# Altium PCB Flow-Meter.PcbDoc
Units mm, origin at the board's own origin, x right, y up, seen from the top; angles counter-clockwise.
Board outline 17 x 19 mm, 2 copper layers (Top Layer, Bottom Layer), stack 1.571 mm thick; 12 components, 7 nets, 36 pads, 15 vias.
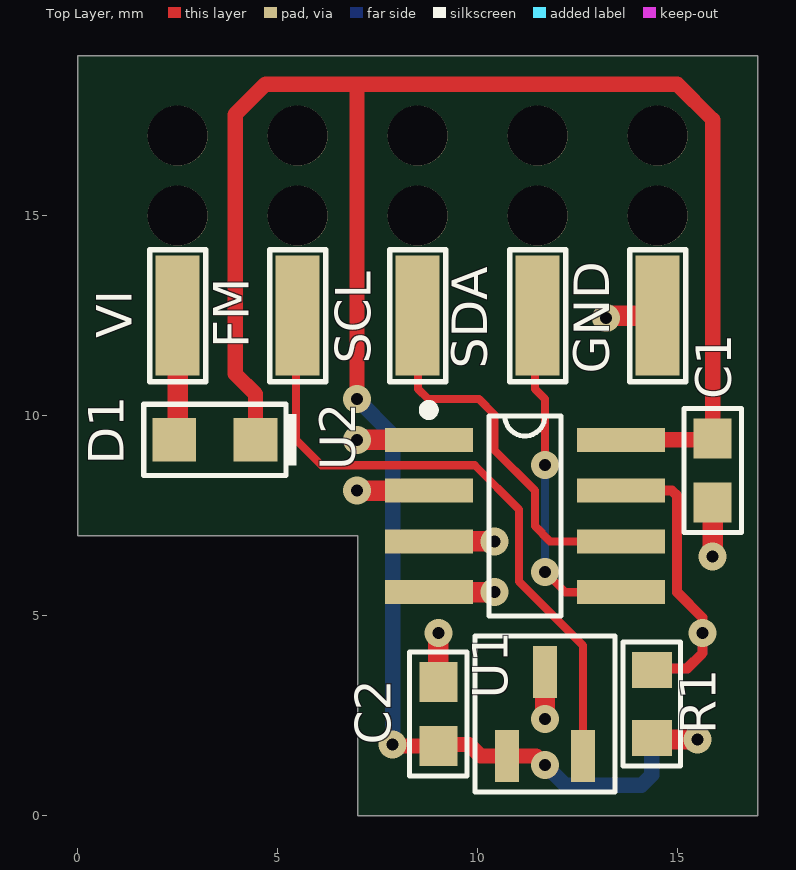
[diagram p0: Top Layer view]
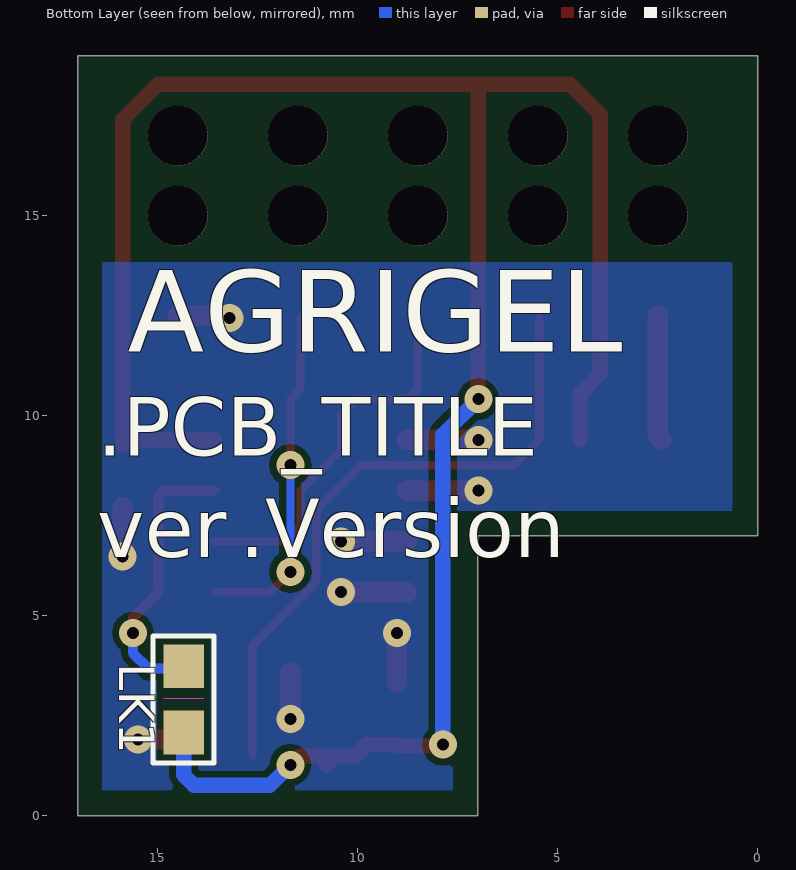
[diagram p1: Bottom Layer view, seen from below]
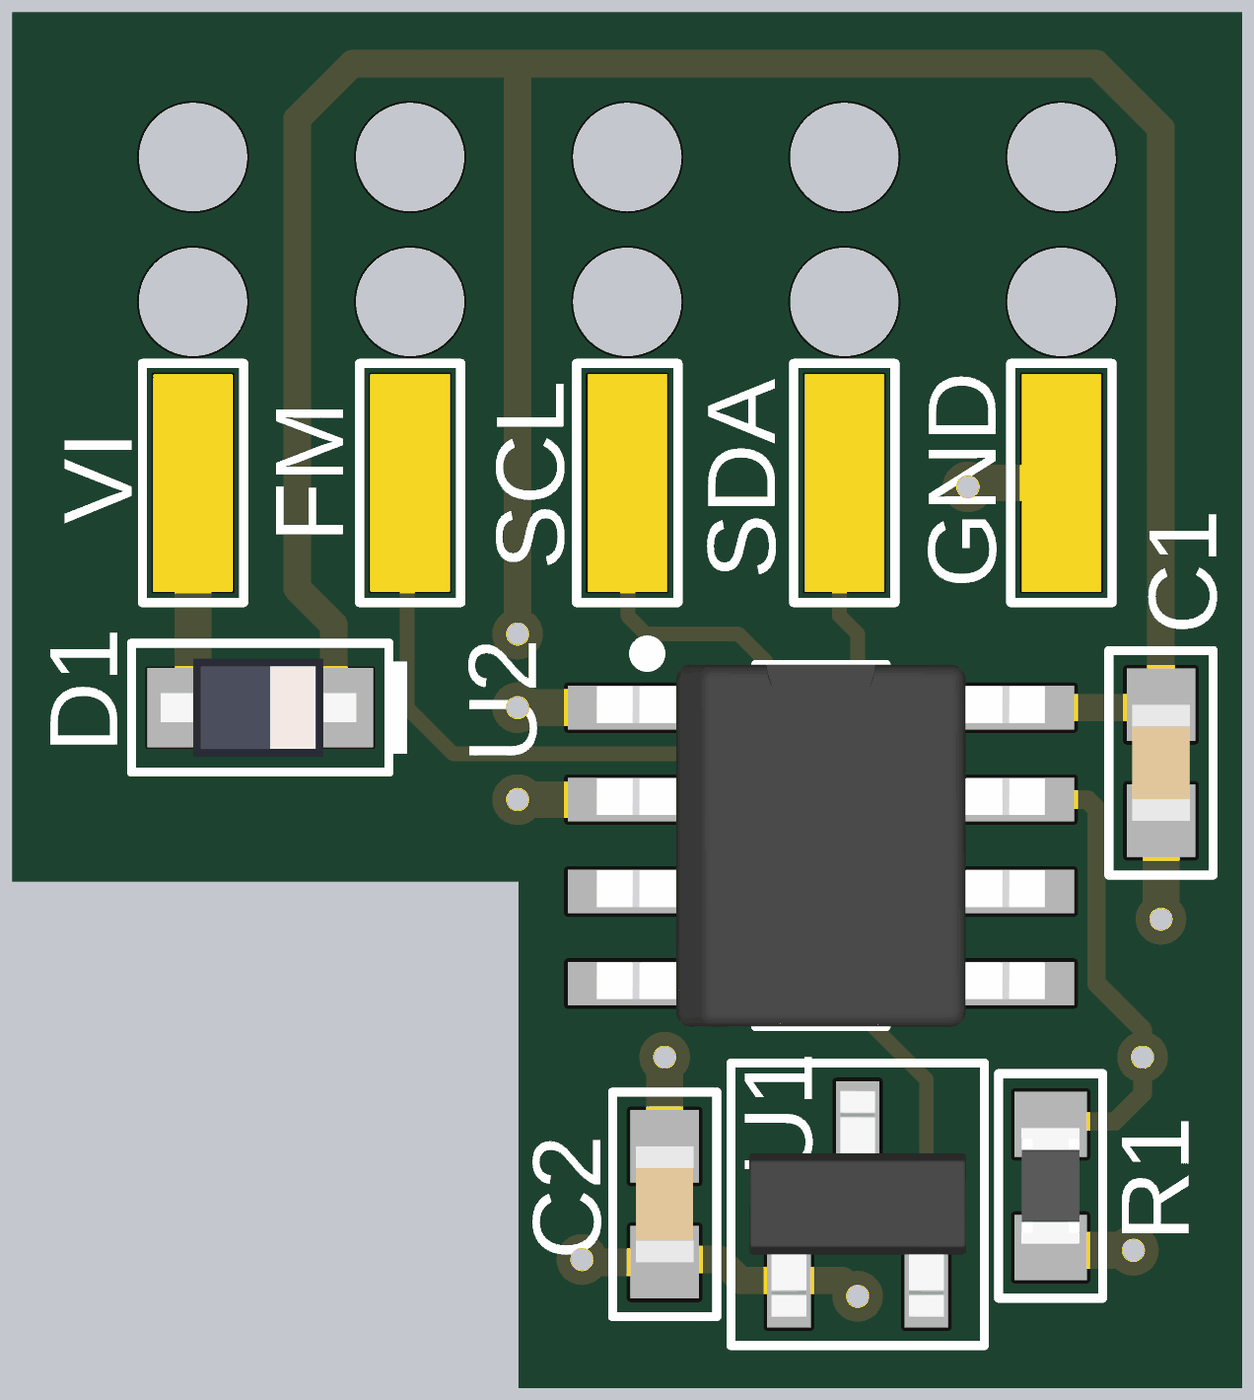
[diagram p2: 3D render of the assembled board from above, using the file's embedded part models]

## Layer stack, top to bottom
Top Layer: signal copper 0.0356
Dielectric: prepreg 1.5, FR-4, Dk 4.2
Bottom Layer: signal copper 0.0356

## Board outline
0,7 0,19 17,19 17,0 7,0 7,7

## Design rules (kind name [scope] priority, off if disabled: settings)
Clearance [All] p1: gap=0.17
ComponentClearance [All] p1: gap=0 collisioncheckmode=3 verticalgap=0.025 showdistances=FALSE
FabricationTestPointUsage TestPointUsage [All] p1: valid=0 allowmultiple=FALSE
FabricationTestpoint Testpoint [All] p1: side=3 testpointundercomponent=TRUE minsize=1.016 maxsize=2.54 preferedsize=1.524 minholesize=0 maxholesize=1.016 preferedholesize=0.813 testpointgrid=0.025 allowsidetop=TRUE allowsidebottom=TRUE usegrid=TRUE gridtolerance=0
HoleSize [All] p1: absolutevalues=TRUE maxlimit=5 minlimit=0.25 maxpercent=80.000 minpercent=20.000
PlaneClearance [All] p1: clearance=0.5
PolygonConnect PolygonConnect_8 [All vs IsNamedPolygon('Top - GND1-HSK')] p1: connectstyle=Direct reliefconductorwidth=0.254 reliefentries=4 polygonreliefangle="90 Angle" airgapwidth=0.254
PolygonConnect PolygonConnect_7 [All vs IsNamedPolygon('Bot - GND1-HSK')] p2: connectstyle=Direct reliefconductorwidth=0.254 reliefentries=4 polygonreliefangle="90 Angle" airgapwidth=0.254
PolygonConnect PolygonConnect_6 [All vs IsNamedPolygon('Bot - GND4a') Or  IsNamedPolygon('Bot - GND2a') Or  IsNamedPolygon('Bot - GND3a')] p3: connectstyle=Direct reliefconductorwidth=0.254 reliefentries=4 polygonreliefangle="90 Angle" airgapwidth=0.254
PolygonConnect PolygonConnect_5 [All vs IsNamedPolygon('Bot - GND1a')] p4: connectstyle=Direct reliefconductorwidth=0.254 reliefentries=4 polygonreliefangle="90 Angle" airgapwidth=0.254
PolygonConnect PolygonConnectVia [All vs isvia] p5: connectstyle=Direct reliefconductorwidth=0.25 reliefentries=4 polygonreliefangle="90 Angle" airgapwidth=0.254
PolygonConnect PolygonConnect_4 [All vs IsNamedPolygon('Bot - GND2')] p6: connectstyle=Relief reliefconductorwidth=0.762 reliefentries=4 polygonreliefangle="90 Angle" airgapwidth=0.254
PolygonConnect PolygonConnect_3 [All vs IsNamedPolygon('Bot - GND1')] p7: connectstyle=Relief reliefconductorwidth=0.762 reliefentries=4 polygonreliefangle="90 Angle" airgapwidth=0.254
PolygonConnect PolygonConnect_2 [All vs IsNamedPolygon('Bot - GND4')] p8: connectstyle=Relief reliefconductorwidth=0.762 reliefentries=4 polygonreliefangle="90 Angle" airgapwidth=0.254
PolygonConnect PolygonConnect_1 [All vs IsNamedPolygon('Bot - GND3')] p9: connectstyle=Relief reliefconductorwidth=0.762 reliefentries=4 polygonreliefangle="90 Angle" airgapwidth=0.254
PolygonConnect [All] p10: connectstyle=Relief reliefconductorwidth=0.4 reliefentries=4 polygonreliefangle="90 Angle" airgapwidth=0.254
RoutingCorners [All] p1: cornerstyle=45-Degree minsetback=2.5 maxsetback=2.5
RoutingVias [All] p1: holewidth=0.3 width=0.7 viastyle="Through Hole" minholewidth=0.3 minwidth=0.7 maxholewidth=0.3 maxwidth=0.7
ShortCircuit ShortCircuit_LK1 [(InComponent('LK1'))] p1: allowed=TRUE
ShortCircuit ShortCircuit_LK2 [(InComponent('LK2'))] p2: allowed=TRUE
ShortCircuit ShortCircuit_LK3 [(InComponent('LK3'))] p3: allowed=TRUE
ShortCircuit [All] p4: allowed=FALSE
SilkToSolderMaskClearance SilkscreenOverComponentPads [IsPad] p1: minsilkscreentomaskgap=0.254 clearancetoexposedcopper=TRUE
SolderMaskExpansion [All] p1: expansion=0.05
Width "Width_High Power" [InNetClass('High Power')] p1: maxlimit=1.5 minlimit=0.5 preferedwidth=1
Width Width_Power [InNetClass('Power')] p2: maxlimit=1 minlimit=0.3 preferedwidth=0.5
Width [All] p3: maxlimit=2 minlimit=0.2 preferedwidth=0.2
20 further rules are at their usual default settings.

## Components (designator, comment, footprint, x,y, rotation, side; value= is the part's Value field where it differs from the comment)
C1 "10nF_C0603_50V_10%_X7R" CAPC0603X85N 15.875,8.636 r270 top
C2 "100nF_C0603_50V_10%_X7R" CAPC0603X85N 9.017,2.54 r90 top
D1 "1N4148WS" SOD323 3.429,9.398 r180 top
FM "Pad-SMD-1.1x3.0mm-H_Rectangle" "PAD-SMD-1.1x3.0mm Rect" 5.5,12.5 r0 top
GND "Pad-SMD-1.1x3.0mm-H_Rectangle" "PAD-SMD-1.1x3.0mm Rect" 14.5,12.5 r0 top
LK1 "Link-SMD-0603-Open" SLINK0603-O 14.351,2.921 r270 bottom
R1 "10K_R0603_1%" RESC0603X60N 14.351,2.794 r270 top
SCL "Pad-SMD-1.1x3.0mm-H_Rectangle" "PAD-SMD-1.1x3.0mm Rect" 8.5,12.5 r0 top
SDA "Pad-SMD-1.1x3.0mm-H_Rectangle" "PAD-SMD-1.1x3.0mm Rect" 11.5,12.5 r0 top
U1 "TLE4946-2K" SOT23 11.684,2.54 r90 top
U2 "24LC02B-I/SN" SO8 11.176,7.493 r0 top
VI "Pad-SMD-1.1x3.0mm-H_Rectangle" "PAD-SMD-1.1x3.0mm Rect" 2.5,12.5 r0 top

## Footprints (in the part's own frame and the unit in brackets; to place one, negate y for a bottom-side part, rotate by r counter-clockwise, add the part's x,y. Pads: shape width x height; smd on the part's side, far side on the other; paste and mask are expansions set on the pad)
CAPC0603X85N [mm] "Chip Capacitor, 0603, 2-Leads, Body 1.6x0.8mm, IPC Medium Density"
  rect 1x0.95 smd paste+0 mask+0.05: 1(-0.8,0) 2(0.8,0)
  silkscreen extent -1.55,-0.72 1.55,0.72, body extent -0.8,-0.4 0.8,0.4, height 0.8
"PAD-SMD-1.1x3.0mm Rect" [mm] "Pad SMD, 1.1x3.0mm Rect"
  rect 1.1x3 smd paste-2.5 mask+0.025: 1(0,0)
  silkscreen extent -0.7,-1.65 0.7,1.65
RESC0603X60N [mm] "Chip Resistor, 0603, 2-Leads, Body 1.6x0.8mm, IPC Medium Density"
  rect 0.9x1 smd paste+0 mask+0.05: 1(-0.85,0) 2(0.85,0)
  silkscreen extent -1.55,-0.72 1.55,0.72, body extent -0.8,-0.4 0.8,0.4, height 0.37
SLINK0603-O [mil] "Solder Link 0603mm Open"
  rect 43x40 smd mask+0.98: 1(-32,0) 2(33,0)
  Top Layer keep-out lines w0.98: 0,19.69 0,-19.69
  silkscreen extent -62,-30 63,30
SO8 [mm] "SOIC, 8-Leads, Body 5.0x4.0mm (max), Pitch 1.27mm, IPC Medium Density"
  rect 2.2x0.6 smd paste+0 mask+0.05: 1(-2.4,1.905) 2(-2.4,0.635) 3(-2.4,-0.635) 4(-2.4,-1.905) 5(2.4,-1.905) 6(2.4,-0.635) 7(2.4,0.635) 8(2.4,1.905)
  silkscreen extent -2.52,-2.5 0.9,2.77, body extent -3.1,-2.5 3.1,2.5, height 1.78
SOD323 [mil] "Diode, SOD323 2-Leads, Body 1.7x1.25mm, IPC Medium Density"
  rect 43x43 smd mask+0.98: 1(-40,0) 2(40,0)
  silkscreen extent -80,-35 70,35, body extent -52,-27 54,27, height 31
SOT23 [mm] "SOT23, 3-Leads, Body 3.0x2.6mm (max), Pitch 0.95mm, IPC Medium Density"
  rect 1.3x0.6 smd paste+0 mask+0.05: 1(-1.05,0.95) 2(-1.05,-0.95) 3(1.05,0)
  silkscreen extent -1.95,-1.75 1.95,1.75, body extent -1.56,-1.5 1.58,1.5, height 1

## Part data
C1: library part 10nF_0603N_50V_10%_X7R_V, "Cap Ceramic X7R"
C2: library part 100nF_0603N_50V_10%_X7R_V, "Cap Ceramic X7R"
D1: library part 1N4148WS_SOD323_H, "Diode Fast Switching Surface Mount"
FM GND SCL SDA VI: "Surface Mount Pad 1.1x3.0mm Rectangle"
LK1: "Link SMD Open 0603"
R1: library part 10K_0603_V, "Resistor Chip SMD"
U1: library part TLE4946-2K_SOT23, "IC Hall Effect Latch"
U2: library part 24LC02B-I/SN-SO8, "IC 2K I2C Serial EEPROM"

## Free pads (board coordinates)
  round 1.5 hole 1.5 unplated mask+0.025: 0(2.5,17) 1(5.5,17) 2(8.5,17) 3(11.5,17) 4(14.5,17) 5(2.5,15) 6(5.5,15) 7(8.5,15) 8(11.5,15) 9(14.5,15)

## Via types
v1: diameter 0.7, hole 0.3, Top Layer to Bottom Layer, tented both sides, 15 vias

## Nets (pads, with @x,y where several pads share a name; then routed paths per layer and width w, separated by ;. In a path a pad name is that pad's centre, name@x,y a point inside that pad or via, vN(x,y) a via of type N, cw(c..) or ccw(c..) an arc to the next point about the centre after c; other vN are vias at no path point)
FLOW_METER: FM.1 U1.2 | length 16.2
  Top Layer w0.203: FM.1@5.461,12.446 5.461,9.398 6.096,8.763 9.925,8.763 11.036,7.652 11.036,5.855 12.634,4.257 U1.2
GND: C1.2 C2.2 GND.1 R1.2 U1.3 U2.1 U2.2 U2.3 U2.4 | length 13
  Top Layer w0.508: v1(6.985,8.128) U2.2 ; v1(6.985,9.398) U2.1 ; U2.4 v1(10.414,5.588) ; U2.3 v1(10.414,6.858) ; C2.2 v1(9.017,4.572) ; v1(11.684,2.413) U1.3 ; v1(13.208,12.446) 13.262,12.5 GND.1 ; R1.2 14.39,1.905 v1(15.494,1.905) ; v1(15.875,6.477) C1.2@15.875,7.709
NetD1_2: D1.2 VI.1 | length 3.1
  Top Layer w0.508: D1.2 2.5,9.485 VI.1
NetLK1_1: LK1.1 R1.1 U2.7 | length 9
  Top Layer w0.254: U2.7 14.859,8.128 14.986,8.001 14.986,5.588 15.621,4.953 v1(15.621,4.572) 15.621,4.064 15.24,3.683 R1.1@14.351,3.683
  Bottom Layer w0.254: LK1.1@14.351,3.683 15.24,3.683 15.621,4.064 v1(15.621,4.572)
SCL: SCL.1 U2.6 | length 9.5
  Top Layer w0.203: SCL.1@8.509,12.446 8.509,10.668 8.763,10.414 10.033,10.414 10.414,10.033 10.414,9.144 11.43,8.128 11.43,7.239 11.811,6.858 U2.6
SDA: SDA.1 U2.5 | length 8.6
  Top Layer w0.203: SDA.1@11.43,12.446 11.43,10.668 11.684,10.414 v1(11.684,8.763) ; v1(11.684,6.096) 12.192,5.588 U2.5
  Bottom Layer w0.203: v1(11.684,6.096) v1(11.684,8.763)
VI: C1.1 C2.1 D1.1 LK1.2 U1.1 U2.8 | length 56.3
  Top Layer w0.381: D1.1 4.445,10.541 3.937,11.049 3.937,17.526 4.699,18.288 6.985,18.288 ; v1(6.985,10.414) 6.985,18.288 ; v1@7.912,1.74 C2.1 ; C2.1@9.017,1.778 9.779,1.778 10.067,1.49 U1.1 11.464,1.49 v1(11.684,1.27) ; U1.1@10.668,1.397 U1.1@10.795,1.27 ; U2.8 C1.1@15.748,9.398 ; C1.1@15.875,9.271 C1.1 15.875,17.399 14.986,18.288 6.985,18.288
  Bottom Layer w0.381: v1(6.985,10.414) 7.874,9.525 v1(7.874,1.778) ; v1(11.684,1.27) 12.192,0.762 14.097,0.762 14.351,1.016 LK1.2@14.351,2.032

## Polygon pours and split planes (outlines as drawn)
GND on Bottom Layer "Bot - GND" (solid, remove dead copper, pour order 2): 0.635,7.62 7.62,7.62 7.62,0.635 16.383,0.635 16.383,13.843 0.635,13.843

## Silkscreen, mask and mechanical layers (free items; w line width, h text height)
Bottom Overlay:
  text "AGRIGEL" at 15.748,10.922 h3.5
  text ".PCB_TITLE" at 16.51,8.509 h2.5
  text ".Version" at 12.954,5.969 h2.5
  text "ver" at 16.51,5.969 h2.5
Board:
  the board outline again, w0.051
Mechanical 15:
  lines w0.051: 0,17 17,17 ; 2.5,15.5 2.5,18.5 ; 5.5,15.5 5.5,18.5 ; 8.5,15.5 8.5,18.5 ; 11.5,15.5 11.5,18.5 ; 14.5,15.5 14.5,18.5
